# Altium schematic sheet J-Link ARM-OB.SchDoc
size A4
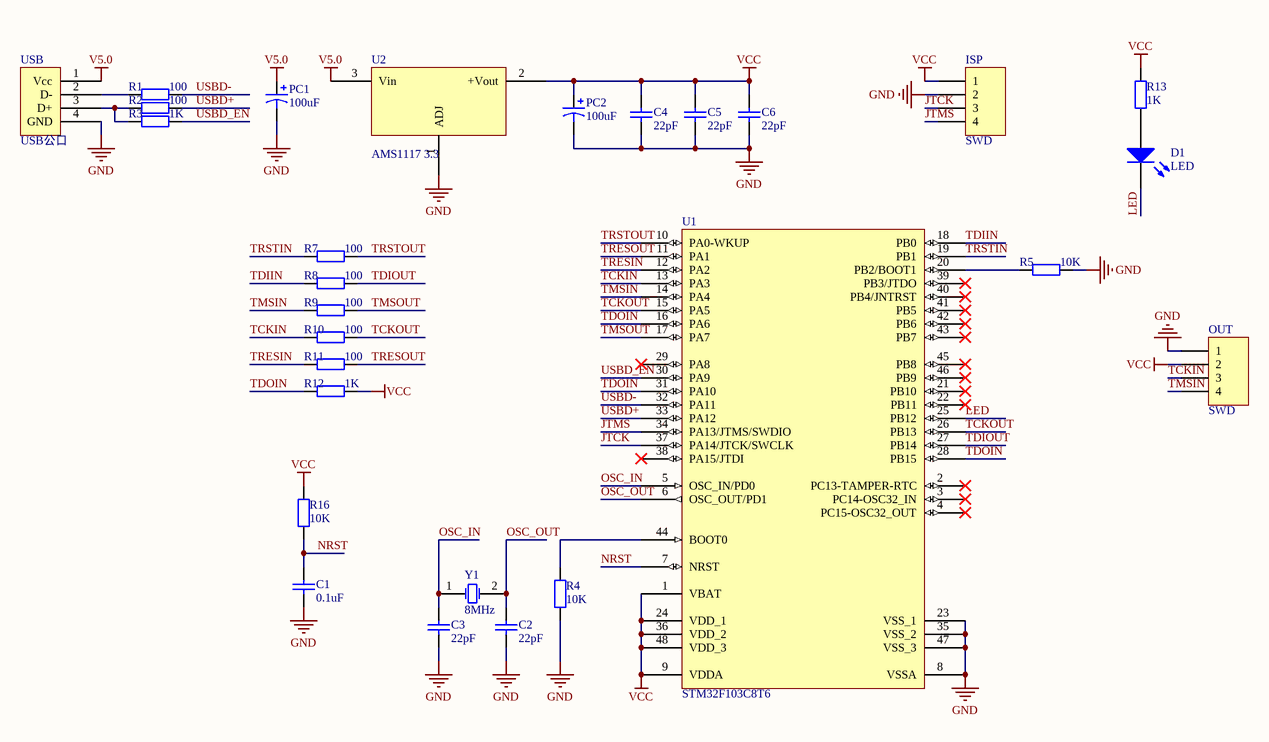
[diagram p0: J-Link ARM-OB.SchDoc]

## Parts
C1  value 0.1uF  [C0603]
C2  value 22pF  [C0603]
C3  value 22pF  [C0603]
C4  value 22pF  [C0603]
C5  value 22pF  [C0603]
C6  value 22pF  [C0603]
D1  LED  [LED0603]
ISP  SWD  [HDR1X4]
OUT  SWD  [HDR1X4]
PC1  value 100uF  [C1206A]
PC2  value 100uF  [C1206A]
R1  value 100  [R0603]
R2  value 100  [R0603]
R3  value 1K  [R0603]
R4  value 10K  [R0603]
R5  value 10K  [R0603]
R7  value 100  [R0603]
R8  value 100  [R0603]
R9  value 100  [R0603]
R10  value 100  [R0603]
R11  value 100  [R0603]
R12  value 1K  [R0603]
R13  value 1K  [R0603]
R16  value 10K  [R0603]
U1  STM32F103C8T6  [LQFP48_N]
U2  AMS1117 3.3  [SOT-223]
USB  USB公口  [USB-H]
Y1  8MHz  [JZ]

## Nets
GND: C1.2 C2.2 C3.2 C4.2 C5.2 C6.2 ISP.2 OUT.1 PC1.2 PC2.2 R4.2 R5.2 U1.8(VSSA) U1.23(VSS_1) U1.35(VSS_2) U1.47(VSS_3) U2.1(ADJ) USB.4(GND)
V5.0: PC1.1 U2.3(Vin) USB.1(Vcc)
VCC: C4.1 C5.1 C6.1 ISP.1 OUT.2 PC2.1 R12.2 R13.2 R16.2 U1.1(VBAT) U1.9(VDDA) U1.24(VDD_1) U1.36(VDD_2) U1.48(VDD_3) U2.2(+Vout)
JTCK: ISP.3 U1.37(PA14/JTCK/SWCLK)
JTMS: ISP.4 U1.34(PA13/JTMS/SWDIO)
LED: D1.2(K) U1.25(PB12)
NRST: C1.1 R16.1 U1.7(NRST)
OSC_IN: C3.1 U1.5(OSC_IN/PD0) Y1.1(OSC1)
OSC_OUT: C2.1 U1.6(OSC_OUT/PD1) Y1.2(OSC2)
TCKIN: OUT.3 R10.1 U1.13(PA3)
TCKOUT: R10.2 U1.15(PA5) U1.26(PB13)
TDIIN: R8.1 U1.18(PB0)
TDIOUT: R8.2 U1.27(PB14)
TDOIN: R12.1 U1.16(PA6) U1.28(PB15) U1.31(PA10)
TMSIN: OUT.4 R9.1 U1.14(PA4)
TMSOUT: R9.2 U1.17(PA7)
TRESIN: R11.1 U1.12(PA2)
TRESOUT: R11.2 U1.11(PA1)
TRSTIN: R7.1 U1.19(PB1)
TRSTOUT: R7.2 U1.10(PA0-WKUP)
USBD+: R2.2 U1.33(PA12)
USBD-: R1.2 U1.32(PA11)
USBD_EN: R3.2 U1.30(PA9)
NetD1_1: D1.1(A) R13.1
NetR1_1: R1.1 USB.2(D-)
NetR2_1: R2.1 R3.1 USB.3(D+)
NetR4_1: R4.1 U1.44(BOOT0)
NetR5_1: R5.1 U1.20(PB2/BOOT1)

Not connected (* = marked no-connect by the designer): U1 2(PC13-TAMPER-RTC)* 3(PC14-OSC32_IN)* 4(PC15-OSC32_OUT)* 21(PB10)* 22(PB11)* 29(PA8)* 38(PA15/JTDI)* 39(PB3/JTDO)* 40(PB4/JNTRST)* 41(PB5)* 42(PB6)* 43(PB7)* 45(PB8)* 46(PB9)*

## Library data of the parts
C1-C6 = Cap: Capacitor
D1 = LED2: Typical RED, GREEN, YELLOW, AMBER GaAs LED
ISP OUT = Header 4: Header, 4-Pin
PC1 PC2 = Cap Pol3: Polarized Capacitor (Surface Mount)
R1-R5 R7-R13 R16 = Res2: Resistor
U1 = STM32F103C8T6: STM32 ARM-based 32-bit MCU with 64 Kbytes Flash, 48-pin LQFP, Industrial Temperature
U2 = LM117T
USB = US
Y1 = XTAL: Crystal Oscillator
